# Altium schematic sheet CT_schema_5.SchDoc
size 255 x 245 mm
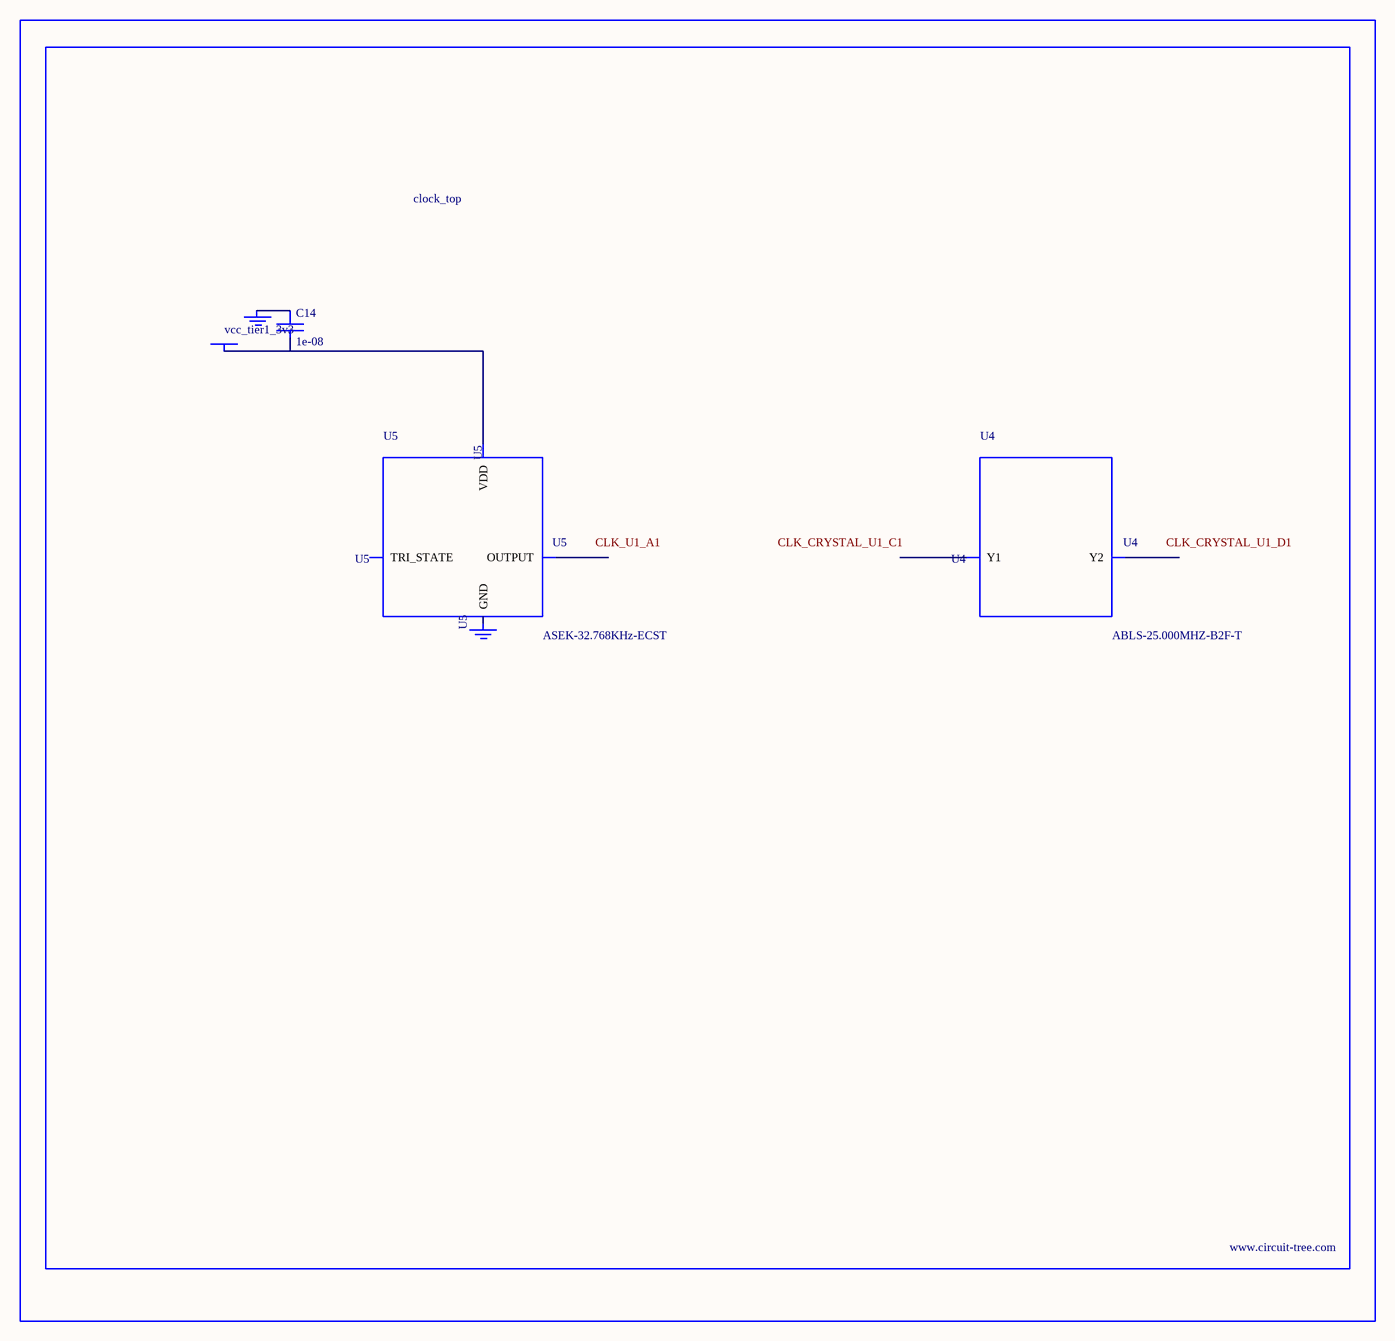
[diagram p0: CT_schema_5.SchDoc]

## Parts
BORDER4  (no value)
C14  1e-08  [C0402]
GND_INSTANCE_4_0  (no value)
GND_INSTANCE_4_1  (no value)
POWER_INSTANCE_4_0  vcc_tier1_3v3
U4  ABLS-25.000MHZ-B2F-T  [ABLS-25.000MHZ-B2F-T]
U5  ASEK-32.768KHz-ECST  [ASEK]

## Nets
NetC14_1: C14.1 GND_INSTANCE_4_0.0(GND)
NetC14_2: C14.2 POWER_INSTANCE_4_0.0(PWR) U5.4(VDD)

Not connected (* = marked no-connect by the designer): GND_INSTANCE_4_1 0(GND); U4 1(Y1) 2(Y2); U5 1(TRI_STATE) 2(GND) 3(OUTPUT)

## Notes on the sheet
- Labels drawn without touching a wire or pin: CLK_CRYSTAL_U1_C1, CLK_CRYSTAL_U1_D1, CLK_U1_A1

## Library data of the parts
BORDER4 = BORDER_PAGE4
C14 = C0402C103K3RAC
GND_INSTANCE_4_0 GND_INSTANCE_4_1 = GND
POWER_INSTANCE_4_0 = PWR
